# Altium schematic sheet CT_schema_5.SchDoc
size 287 x 160 mm
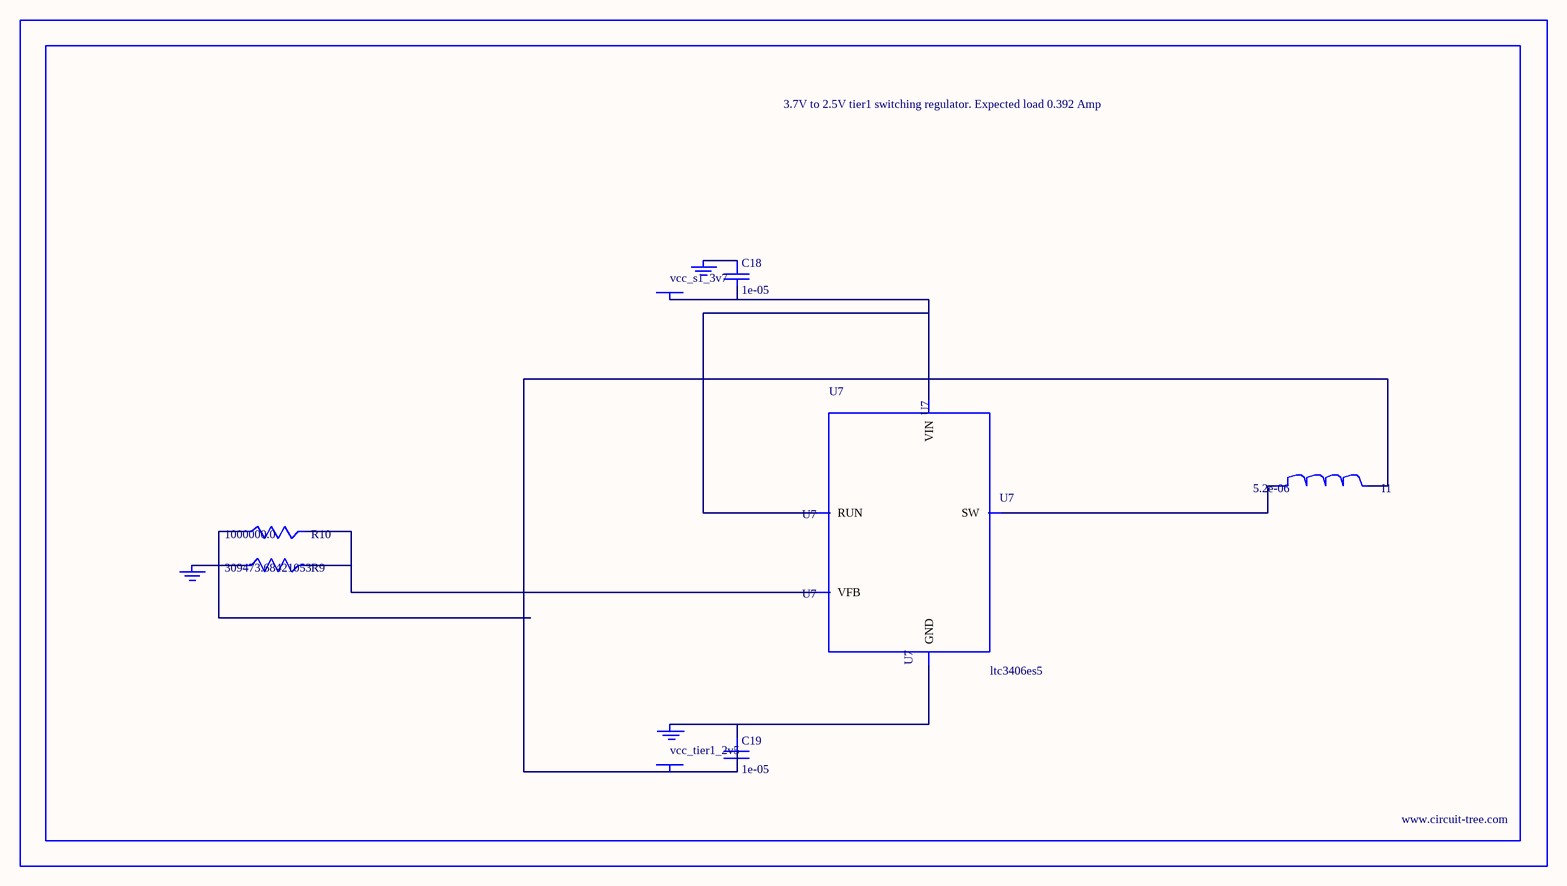
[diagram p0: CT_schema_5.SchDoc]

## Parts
BORDER4  (no value)
C18  1e-05  [C0805]
C19  1e-05  [C0805]
GND_INSTANCE_4_0  (no value)
GND_INSTANCE_4_1  (no value)
GND_INSTANCE_4_2  (no value)
I1  5.2e-06  [DR1040]
POWER_INSTANCE_4_0  vcc_tier1_2v5
POWER_INSTANCE_4_1  vcc_s1_3v7
R9  309473.68421053  [R0603]
R10  1000000.0  [R0603]
U7  ltc3406es5  [TSOT-23-5]

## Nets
NetC18_1: C18.1 GND_INSTANCE_4_1.0(GND)
NetC18_2: C18.2 POWER_INSTANCE_4_1.0(PWR) U7.1(RUN) U7.4(VIN)
NetC19_1: C19.1 GND_INSTANCE_4_0.0(GND) U7.2(GND)
NetC19_2: C19.2 I1.2 POWER_INSTANCE_4_0.0(PWR) R10.1
NetGND_INSTANCE_4_2_0: GND_INSTANCE_4_2.0(GND) R9.1
NetI1_1: I1.1 U7.3(SW)
NetR9_2: R9.2 R10.2 U7.5(VFB)

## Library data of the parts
BORDER4 = BORDER_PAGE4
C18 C19 = C0805C106K8RACTU
GND_INSTANCE_4_0-GND_INSTANCE_4_2 = GND
I1 = DR1040-5R2-R
POWER_INSTANCE_4_0 POWER_INSTANCE_4_1 = PWR
R9 = R9
R10 = RC0603JR-071ML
